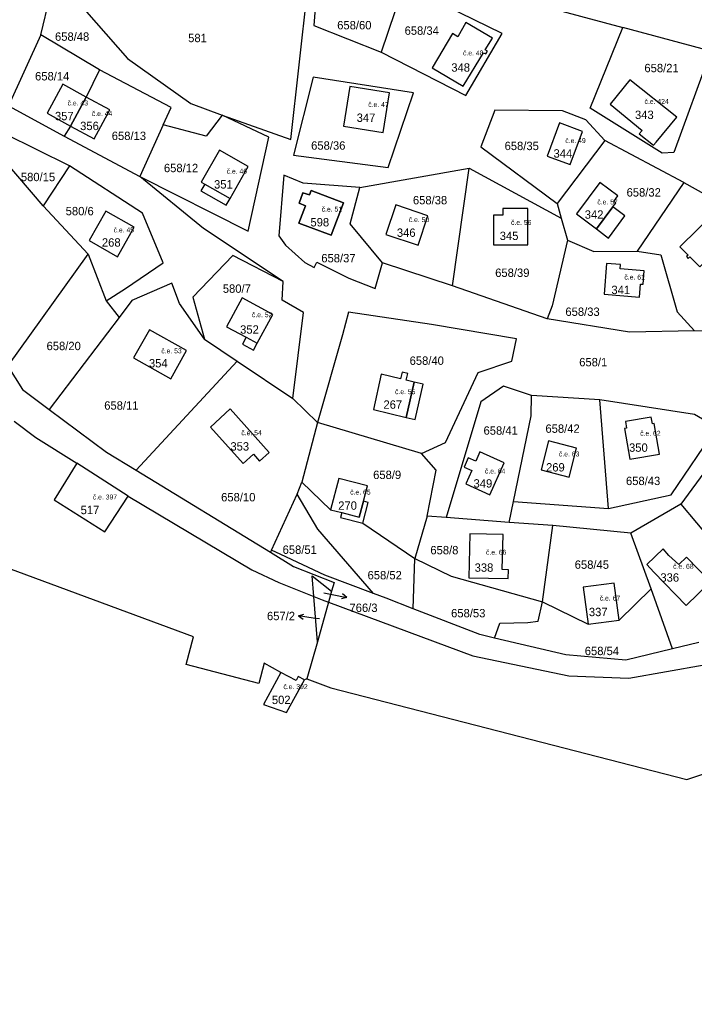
# Model space of a CAD drawing. Extents: x -887272 to -880188, y -1026687 to -1021896.
# Drawn here: x -883908.9 to -883771.9, y -1024223.4 to -1024025.9 of the extents above; entities that cross this region are included whole.
import ezdxf

# ---------------------------------------------------------------- set-up
doc = ezdxf.new("R2010")
doc.units = 0
for name, color, linetype in [('Definiční body', 7, 'Continuous'), ('Hranice parcel', 7, 'Continuous'), ('Parcelní čísla', 7, 'Continuous'), ('Polygon budovy', 7, 'Continuous'), ('Pop  PČ popisy', 7, 'Continuous'), ('Vnitřní kresba', 7, 'Continuous')]:
    doc.layers.add(name, color=color, linetype=linetype)

msp = doc.modelspace()

# ---------------------------------------------------------------- linework, layer by layer
at = {"layer": 'Hranice parcel'}
for p, q in [((-883904.58, -1024028.99), (-883901.68, -1024017.03)), ((-883832.76, -1024024.32), (-883835.54, -1024032.54)), ((-883904.58, -1024028.99), (-883911.13, -1024043.4)), ((-883892.65, -1024036.09), (-883904.58, -1024028.99)), ((-883768.62, -1024032.31), (-883786.49, -1024027.54)), ((-883892.65, -1024036.09), (-883895.35, -1024041.64)), ((-883895.35, -1024041.64), (-883898.54, -1024047.52)), ((-883911.13, -1024043.4), (-883899.81, -1024049.6)), ((-883898.54, -1024047.52), (-883899.81, -1024049.6)), ((-883879.74, -1024047.28), (-883884.47, -1024057.79)), ((-883898.73, -1024055.6), (-883911.85, -1024049.13)), ((-883899.81, -1024049.6), (-883884.47, -1024057.79)), ((-883790.11, -1024050.47), (-883799.82, -1024063.26)), ((-883774.14, -1024058.98), (-883790.11, -1024050.47)), ((-883815.27, -1024051.72), (-883799.82, -1024063.26)), ((-883904.07, -1024063.74), (-883912, -1024054.42)), ((-883898.73, -1024055.6), (-883904.07, -1024063.74)), ((-883839.82, -1024059.97), (-883817.65, -1024056.09)), ((-883821.04, -1024079.95), (-883817.65, -1024056.09)), ((-883817.65, -1024056.09), (-883798.98, -1024066.23)), ((-883774.14, -1024058.98), (-883783.59, -1024072.91)), ((-883904.07, -1024063.74), (-883895, -1024073.52)), ((-883799.82, -1024063.26), (-883798.98, -1024066.23)), ((-883798.98, -1024066.23), (-883797.72, -1024070.66)), ((-883797.72, -1024070.66), (-883800.86, -1024084)), ((-883911.25, -1024096.23), (-883895, -1024073.52)), ((-883895, -1024073.52), (-883891.31, -1024082.96)), ((-883821.04, -1024079.95), (-883835.23, -1024075.29)), ((-883801.81, -1024086.66), (-883821.04, -1024079.95)), ((-883891.31, -1024082.96), (-883888.71, -1024086.37)), ((-883886.12, -1024082.95), (-883888.71, -1024086.37)), ((-883800.86, -1024084), (-883801.81, -1024086.66)), ((-883888.71, -1024086.37), (-883902.86, -1024105.05)), ((-883785.14, -1024089.32), (-883801.81, -1024086.66)), ((-883771.96, -1024089.06), (-883785.14, -1024089.32)), ((-883871.37, -1024090.78), (-883864.73, -1024095.24)), ((-883864.73, -1024095.24), (-883885.25, -1024117.37)), ((-883864.73, -1024095.24), (-883853.46, -1024102.81)), ((-883791.15, -1024103.07), (-883805.04, -1024102.17)), ((-883848.46, -1024107.7), (-883853.46, -1024102.81)), ((-883789.37, -1024125.15), (-883791.15, -1024103.07)), ((-883848.46, -1024107.7), (-883851.6, -1024119.81)), ((-883827.31, -1024113.95), (-883848.46, -1024107.7)), ((-883886.86, -1024122.61), (-883897.3, -1024115.95)), ((-883885.25, -1024117.37), (-883857.97, -1024134.02)), ((-883852.59, -1024122.24), (-883851.6, -1024119.81)), ((-883851.6, -1024119.81), (-883845.79, -1024125.37)), ((-883857.76, -1024133.58), (-883852.59, -1024122.24)), ((-883809.55, -1024127.94), (-883808.64, -1024123.74)), ((-883808.64, -1024123.74), (-883789.37, -1024125.15)), ((-883774.69, -1024124.26), (-883784.9, -1024130.11)), ((-883826.22, -1024126.68), (-883828.69, -1024135.31)), ((-883822.34, -1024126.95), (-883826.22, -1024126.68)), ((-883809.55, -1024127.94), (-883822.34, -1024126.95)), ((-883800.69, -1024128.6), (-883809.55, -1024127.94)), ((-883839.24, -1024128.12), (-883828.69, -1024135.31)), ((-883802.78, -1024144.09), (-883800.69, -1024128.6)), ((-883784.9, -1024130.11), (-883800.69, -1024128.6)), ((-883780.77, -1024141.46), (-883784.9, -1024130.11)), ((-883857.76, -1024133.58), (-883857.97, -1024134.02)), ((-883829.01, -1024145.48), (-883828.69, -1024135.31)), ((-883845.58, -1024141.88), (-883846.21, -1024144.12)), ((-883794.52, -1024141.12), (-883793.52, -1024148.63)), ((-883787.26, -1024147.8), (-883780.77, -1024141.46)), ((-883776.38, -1024153.62), (-883780.77, -1024141.46)), ((-883848.47, -1024152.18), (-883849.17, -1024142.97)), ((-883846.21, -1024144.12), (-883848.47, -1024152.18)), ((-883802.78, -1024144.09), (-883793.52, -1024148.63)), ((-883793.52, -1024148.63), (-883787.26, -1024147.8)), ((-883848.47, -1024152.18), (-883850.59, -1024159.71)), ((-883771.09, -1024152.35), (-883776.38, -1024153.62)), ((-883850.59, -1024159.71), (-883851.11, -1024159.93))]:
    msp.add_line(p, q, dxfattribs=at)
for points in [[(-883899.62, -1024008.57), (-883860.9, -1024017.44), (-883848.52, -1024018.46), (-883830.95, -1024018.96), (-883822.3, -1024020.14), (-883798.84, -1024024.24), (-883786.49, -1024027.54)], [(-883867.76, -1024045.3), (-883853.82, -1024050.22), (-883850.5, -1024019.86), (-883889.5, -1024014.8), (-883900.86, -1024013.67)], [(-883901.68, -1024017.03), (-883886.96, -1024033.84), (-883874.14, -1024042.96), (-883867.76, -1024045.3)], [(-883835.54, -1024032.54), (-883818.36, -1024041.34), (-883811, -1024028.73), (-883830.95, -1024018.96), (-883832.76, -1024024.32)], [(-883832.76, -1024024.32), (-883848.72, -1024020.95), (-883849.18, -1024027.12), (-883835.54, -1024032.54)], [(-883814.31, -1024032.88), (-883813.98, -1024032.34), (-883814.4, -1024032.08), (-883812.92, -1024029.69), (-883818.33, -1024026.51), (-883820, -1024029.39), (-883821.08, -1024028.76), (-883825.2, -1024035.73), (-883818.87, -1024039.46), (-883814.73, -1024032.63), (-883814.31, -1024032.88)], [(-883768.62, -1024032.31), (-883776.16, -1024052.87), (-883778.5, -1024053.04), (-883793.12, -1024043.9), (-883786.49, -1024027.54)], [(-883879.74, -1024047.28), (-883878.15, -1024043.75), (-883892.65, -1024036.09)], [(-883895.35, -1024041.64), (-883900.14, -1024039.05), (-883903.32, -1024044.93), (-883898.54, -1024047.52)], [(-883853.32, -1024053.42), (-883834.12, -1024055.92), (-883828.96, -1024040.76), (-883849.32, -1024037.62), (-883853.32, -1024053.42)], [(-883785.08, -1024038.15), (-883789.08, -1024043.05), (-883782.58, -1024048.4), (-883783.15, -1024049.1), (-883780.27, -1024051.42), (-883779.72, -1024050.76), (-883775.54, -1024045.69), (-883785.08, -1024038.15)], [(-883843.14, -1024047.53), (-883835.09, -1024048.8), (-883833.83, -1024040.78), (-883841.88, -1024039.52), (-883843.14, -1024047.53)], [(-883898.54, -1024047.52), (-883893.75, -1024050.11), (-883890.57, -1024044.23), (-883895.35, -1024041.64)], [(-883790.11, -1024050.47), (-883793.99, -1024046.26), (-883798.72, -1024044.43), (-883812.43, -1024044.32), (-883815.27, -1024051.72)], [(-883884.47, -1024057.79), (-883862.5, -1024068.88), (-883858.34, -1024049.76), (-883867.76, -1024045.3)], [(-883867.76, -1024045.3), (-883871.06, -1024049.54), (-883879.74, -1024047.28)], [(-883794.66, -1024048.64), (-883799.35, -1024046.89), (-883801.84, -1024053.6), (-883797.16, -1024055.35), (-883794.66, -1024048.64)], [(-883866.19, -1024062.24), (-883862.5, -1024055.71), (-883868.29, -1024052.44), (-883872.04, -1024058.94), (-883871.33, -1024059.34), (-883872.1, -1024060.68), (-883866.95, -1024063.59), (-883866.19, -1024062.24)], [(-883891.31, -1024082.96), (-883887.41, -1024080.46), (-883879.76, -1024075.27), (-883883.92, -1024065.17), (-883898.73, -1024055.6)], [(-883855.39, -1024079.08), (-883871.6, -1024068.28), (-883884.47, -1024057.79)], [(-883839.82, -1024059.97), (-883851.38, -1024059.11), (-883855.27, -1024057.51), (-883856.27, -1024069.78), (-883854.92, -1024071.68), (-883851, -1024075.19)], [(-883788.54, -1024063.9), (-883787.94, -1024063.09), (-883788.29, -1024062.81), (-883787.49, -1024061.68), (-883791.17, -1024058.95), (-883795.9, -1024065.32), (-883791.86, -1024068.39), (-883789.42, -1024070.24), (-883786.08, -1024065.72), (-883788.54, -1024063.9)], [(-883851.41, -1024061.08), (-883850.08, -1024061.51), (-883849.74, -1024060.63), (-883843.18, -1024063.09), (-883845.65, -1024069.66), (-883852.21, -1024067.21), (-883850.9, -1024063.73), (-883852.14, -1024063.2), (-883851.41, -1024061.08)], [(-883846.21, -1024144.12), (-883816.92, -1024155.06), (-883797.46, -1024159.1), (-883785.24, -1024159.54), (-883770.02, -1024156.86), (-883754.54, -1024149.76), (-883741.82, -1024138.86), (-883718.28, -1024114.56), (-883704.22, -1024101.36), (-883679.66, -1024088.08), (-883640.76, -1024076.54), (-883629.62, -1024072.06), (-883617.24, -1024060.68)], [(-883835.23, -1024075.29), (-883841.84, -1024067.33), (-883839.82, -1024059.97)], [(-883774.14, -1024058.98), (-883765.97, -1024063.54), (-883750.88, -1024077.62), (-883742.25, -1024090.97), (-883754.31, -1024089.52), (-883771.96, -1024089.06)], [(-883889.05, -1024074.03), (-883885.63, -1024068.04), (-883891.36, -1024064.77), (-883894.78, -1024070.76), (-883889.05, -1024074.03)], [(-883832.57, -1024063.54), (-883834.56, -1024069.52), (-883828.01, -1024071.7), (-883826.02, -1024065.72), (-883832.57, -1024063.54)], [(-883805.74, -1024071.6), (-883805.76, -1024064.25), (-883810.86, -1024064.26), (-883810.86, -1024065.59), (-883812.76, -1024065.6), (-883812.74, -1024071.62), (-883805.74, -1024071.6)], [(-883773.25, -1024074.38), (-883772.9, -1024074.05), (-883770.89, -1024076.11), (-883769.13, -1024074.41), (-883766.95, -1024076.58), (-883761.97, -1024071.47), (-883765.87, -1024067.35), (-883765.62, -1024067.08), (-883767.68, -1024064.92), (-883774.9, -1024072), (-883773.24, -1024073.7), (-883773.59, -1024074.02), (-883773.25, -1024074.38)], [(-883797.72, -1024070.66), (-883792.36, -1024072.96), (-883783.59, -1024072.91)], [(-883855.39, -1024079.08), (-883865.64, -1024073.78), (-883873.75, -1024082.22), (-883871.37, -1024090.78)], [(-883783.59, -1024072.91), (-883778.79, -1024073.63), (-883775.45, -1024085.25), (-883771.96, -1024089.06)], [(-883851, -1024075.19), (-883849.14, -1024076.21), (-883848.6, -1024075.14), (-883842.11, -1024078.39)], [(-883842.11, -1024078.39), (-883836.75, -1024080.5), (-883835.23, -1024075.29)], [(-883787.01, -1024076.49), (-883786.94, -1024075.65), (-883789.78, -1024075.42), (-883790.28, -1024081.65), (-883783.12, -1024082.22), (-883782.9, -1024079.58), (-883782.39, -1024079.62), (-883782.18, -1024076.88), (-883787.01, -1024076.49)], [(-883871.37, -1024090.78), (-883876.44, -1024083.54), (-883877.98, -1024079.41), (-883886.12, -1024082.95)], [(-883853.46, -1024102.81), (-883851.26, -1024085.39), (-883855.59, -1024082.86), (-883855.39, -1024079.08)], [(-883863.67, -1024091.75), (-883861.44, -1024092.99), (-883860.69, -1024091.61), (-883857.51, -1024085.77), (-883863.7, -1024082.4), (-883866.88, -1024088.24), (-883862.93, -1024090.39), (-883863.67, -1024091.75)], [(-883827.31, -1024113.95), (-883822.48, -1024111.73), (-883815.82, -1024097.56), (-883809.04, -1024095.22), (-883808.05, -1024090.68), (-883825.31, -1024087.78), (-883842.14, -1024085.28), (-883843.37, -1024089.91), (-883848.46, -1024107.7)], [(-883878.22, -1024098.8), (-883875.02, -1024093.1), (-883882.54, -1024088.88), (-883885.74, -1024094.58), (-883878.22, -1024098.8)], [(-883911.25, -1024096.23), (-883908.31, -1024100.98), (-883902.86, -1024105.05)], [(-883835.5, -1024097.87), (-883837.09, -1024105.03), (-883830.43, -1024106.65), (-883828.63, -1024107.09), (-883827.02, -1024099.91), (-883828.8, -1024099.48), (-883830.44, -1024099.09), (-883830.12, -1024097.75), (-883831.29, -1024097.47), (-883831.61, -1024098.8), (-883835.5, -1024097.87)], [(-883805.04, -1024102.17), (-883810.73, -1024100.34), (-883815.28, -1024103.49), (-883822.34, -1024126.95)], [(-883808.64, -1024123.74), (-883805.07, -1024106.32), (-883805.04, -1024102.17)], [(-883789.37, -1024125.15), (-883776.68, -1024122.39), (-883767.41, -1024108.72), (-883771.96, -1024106.03), (-883791.15, -1024103.07)], [(-883902.86, -1024105.05), (-883891.27, -1024113.69), (-883885.25, -1024117.37)], [(-883870.17, -1024108.63), (-883863.54, -1024116.02), (-883861.44, -1024114.13), (-883860.21, -1024115.5), (-883858.25, -1024113.75), (-883866.19, -1024104.9), (-883870.17, -1024108.63)], [(-883909.98, -1024107.42), (-883905.62, -1024110.7), (-883897.3, -1024115.95)], [(-883780.72, -1024106.61), (-883785.96, -1024107.49), (-883785.74, -1024108.83), (-883786.17, -1024108.9), (-883785.05, -1024115.09), (-883779.07, -1024114.08), (-883780.12, -1024107.89), (-883780.5, -1024107.95), (-883780.72, -1024106.61)], [(-883755.65, -1024112.37), (-883763.88, -1024109.51), (-883774.69, -1024124.26)], [(-883803.06, -1024117.29), (-883797.35, -1024118.75), (-883795.86, -1024112.89), (-883801.57, -1024111.43), (-883803.06, -1024117.29)], [(-883826.22, -1024126.68), (-883824.36, -1024117.36), (-883827.31, -1024113.95)], [(-883816.31, -1024115.53), (-883817.88, -1024114.84), (-883818.71, -1024116.74), (-883817.14, -1024117.43), (-883818.33, -1024120.16), (-883813.45, -1024122.35), (-883810.54, -1024115.86), (-883815.48, -1024113.64), (-883816.31, -1024115.53)], [(-883897.3, -1024115.95), (-883901.84, -1024123.36), (-883891.56, -1024129.87), (-883886.86, -1024122.61)], [(-883839.24, -1024128.12), (-883838.14, -1024123.89), (-883839.11, -1024123.64), (-883838.31, -1024120.56), (-883844.14, -1024119.04), (-883845.79, -1024125.37)], [(-883886.86, -1024122.61), (-883861.76, -1024137.6), (-883856.28, -1024140.14), (-883849.17, -1024142.97)], [(-883837.08, -1024142.37), (-883848.38, -1024129.33), (-883852.59, -1024122.24)], [(-883845.79, -1024125.37), (-883843.51, -1024125.96), (-883843.76, -1024126.94), (-883839.24, -1024128.12)], [(-883774.69, -1024124.26), (-883768.39, -1024131.8), (-883765.84, -1024134.88)], [(-883810.78, -1024130.4), (-883817.56, -1024130.29), (-883817.73, -1024139.21), (-883809.73, -1024139.36), (-883809.66, -1024137.55), (-883810.95, -1024137.52), (-883810.78, -1024130.4)], [(-883855.91, -1024158.43), (-883859.24, -1024156.52), (-883860.34, -1024160.64), (-883875.1, -1024156.8), (-883873.62, -1024151.2), (-883922.82, -1024133), (-883946.68, -1024157.76), (-883998.42, -1024167.88), (-884017.26, -1024191.06), (-884045.27, -1024222.29), (-884069.78, -1024223.36)], [(-883837.08, -1024142.37), (-883846.93, -1024138.63), (-883855.9, -1024134.45), (-883857.76, -1024133.58)], [(-883777.14, -1024134.64), (-883778.34, -1024133.34), (-883781.61, -1024136.5)], [(-883857.97, -1024134.02), (-883853.29, -1024136.88), (-883845.09, -1024140.15), (-883845.58, -1024141.88)], [(-883828.69, -1024135.31), (-883821.35, -1024138.89), (-883802.78, -1024144.09)], [(-883773.56, -1024134.99), (-883775.1, -1024136.47), (-883777.14, -1024134.64)], [(-883773.62, -1024144.81), (-883768.71, -1024140), (-883773.56, -1024134.99)], [(-883781.61, -1024136.5), (-883780.21, -1024138.05), (-883773.62, -1024144.81)], [(-883849.17, -1024142.97), (-883849.49, -1024138.77), (-883845.58, -1024141.88)], [(-883787.26, -1024147.8), (-883788.26, -1024140.29), (-883794.52, -1024141.12)], [(-883849.17, -1024142.97), (-883847.5, -1024143.64), (-883846.21, -1024144.12)], [(-883829.01, -1024145.48), (-883834.53, -1024143.33), (-883837.08, -1024142.37)], [(-883812.51, -1024151.44), (-883815.49, -1024150.73), (-883829.01, -1024145.48)], [(-883812.51, -1024151.44), (-883811.42, -1024148.42), (-883805.74, -1024148.27), (-883803.69, -1024147.97), (-883802.78, -1024144.09)], [(-883776.38, -1024153.62), (-883785.87, -1024155.89), (-883798.06, -1024154.86), (-883812.51, -1024151.44)], [(-883855.91, -1024158.43), (-883859.37, -1024164.93), (-883854.7, -1024166.54), (-883851.11, -1024159.93)], [(-883851.11, -1024159.93), (-883852.36, -1024159.25), (-883852.76, -1024160.05), (-883855.91, -1024158.43)], [(-883850.59, -1024159.71), (-883845.76, -1024161.5), (-883773.48, -1024180.1), (-883759.24, -1024175.32)]]:
    msp.add_lwpolyline(points, dxfattribs=at)
at = {"layer": 'Polygon budovy'}
for points in [[(-883818.87, -1024039.46), (-883814.73, -1024032.63), (-883814.31, -1024032.88), (-883813.98, -1024032.34), (-883814.4, -1024032.08), (-883812.92, -1024029.69), (-883818.33, -1024026.51), (-883820, -1024029.39), (-883821.08, -1024028.76), (-883825.2, -1024035.73)], [(-883903.32, -1024044.93), (-883898.54, -1024047.52), (-883895.35, -1024041.64), (-883900.14, -1024039.05)], [(-883775.54, -1024045.69), (-883785.08, -1024038.15), (-883789.08, -1024043.05), (-883782.58, -1024048.4), (-883783.15, -1024049.1), (-883780.27, -1024051.42), (-883779.72, -1024050.76)], [(-883841.88, -1024039.52), (-883843.14, -1024047.53), (-883835.09, -1024048.8), (-883833.83, -1024040.78)], [(-883895.35, -1024041.64), (-883898.54, -1024047.52), (-883893.75, -1024050.11), (-883890.57, -1024044.23)], [(-883801.84, -1024053.6), (-883797.16, -1024055.35), (-883794.66, -1024048.64), (-883799.35, -1024046.89)], [(-883862.5, -1024055.71), (-883868.29, -1024052.44), (-883872.04, -1024058.94), (-883871.33, -1024059.34), (-883866.19, -1024062.24)], [(-883788.54, -1024063.9), (-883787.94, -1024063.09), (-883788.29, -1024062.81), (-883787.49, -1024061.68), (-883791.17, -1024058.95), (-883795.9, -1024065.32), (-883791.86, -1024068.39)], [(-883849.74, -1024060.63), (-883850.08, -1024061.51), (-883851.41, -1024061.08), (-883852.14, -1024063.2), (-883850.9, -1024063.73), (-883852.21, -1024067.21), (-883845.65, -1024069.66), (-883843.18, -1024063.09)], [(-883891.36, -1024064.77), (-883894.78, -1024070.76), (-883889.05, -1024074.03), (-883885.63, -1024068.04)], [(-883834.56, -1024069.52), (-883828.01, -1024071.7), (-883826.02, -1024065.72), (-883832.57, -1024063.54)], [(-883805.76, -1024064.25), (-883810.86, -1024064.26), (-883810.86, -1024065.59), (-883812.76, -1024065.6), (-883812.74, -1024071.62), (-883805.74, -1024071.6)], [(-883773.59, -1024074.02), (-883773.25, -1024074.38), (-883772.9, -1024074.05), (-883770.89, -1024076.11), (-883769.13, -1024074.41), (-883765.16, -1024070.5), (-883767.03, -1024068.53), (-883765.87, -1024067.35), (-883765.62, -1024067.08), (-883767.68, -1024064.92), (-883774.9, -1024072), (-883773.24, -1024073.7)], [(-883789.78, -1024075.42), (-883790.28, -1024081.65), (-883783.12, -1024082.22), (-883782.9, -1024079.58), (-883782.39, -1024079.62), (-883782.18, -1024076.88), (-883787.01, -1024076.49), (-883786.94, -1024075.65)], [(-883863.7, -1024082.4), (-883866.88, -1024088.24), (-883862.93, -1024090.39), (-883860.69, -1024091.61), (-883857.51, -1024085.77)], [(-883882.54, -1024088.88), (-883885.74, -1024094.58), (-883878.22, -1024098.8), (-883875.02, -1024093.1)], [(-883837.09, -1024105.03), (-883830.43, -1024106.65), (-883828.8, -1024099.48), (-883830.44, -1024099.09), (-883830.12, -1024097.75), (-883831.29, -1024097.47), (-883831.61, -1024098.8), (-883835.5, -1024097.87)], [(-883866.19, -1024104.9), (-883870.17, -1024108.63), (-883863.54, -1024116.02), (-883861.44, -1024114.13), (-883860.21, -1024115.5), (-883858.25, -1024113.75)], [(-883785.96, -1024107.49), (-883785.74, -1024108.83), (-883786.17, -1024108.9), (-883785.05, -1024115.09), (-883779.07, -1024114.08), (-883780.12, -1024107.89), (-883780.5, -1024107.95), (-883780.72, -1024106.61)], [(-883801.57, -1024111.43), (-883803.06, -1024117.29), (-883797.35, -1024118.75), (-883795.86, -1024112.89)], [(-883815.48, -1024113.64), (-883816.31, -1024115.53), (-883817.88, -1024114.84), (-883818.71, -1024116.74), (-883817.14, -1024117.43), (-883818.33, -1024120.16), (-883813.45, -1024122.35), (-883810.54, -1024115.86)], [(-883897.3, -1024115.95), (-883901.84, -1024123.36), (-883891.56, -1024129.87), (-883886.86, -1024122.61)], [(-883845.79, -1024125.37), (-883843.51, -1024125.96), (-883839.96, -1024126.89), (-883839.11, -1024123.64), (-883838.31, -1024120.56), (-883844.14, -1024119.04)], [(-883817.73, -1024139.21), (-883809.73, -1024139.36), (-883809.66, -1024137.55), (-883810.95, -1024137.52), (-883810.78, -1024130.4), (-883817.56, -1024130.29)], [(-883780.21, -1024138.05), (-883773.62, -1024144.81), (-883768.71, -1024140), (-883773.56, -1024134.99), (-883775.1, -1024136.47), (-883777.14, -1024134.64), (-883778.34, -1024133.34), (-883781.61, -1024136.5)], [(-883794.52, -1024141.12), (-883793.52, -1024148.63), (-883787.26, -1024147.8), (-883788.26, -1024140.29)], [(-883855.91, -1024158.43), (-883859.37, -1024164.93), (-883854.7, -1024166.54), (-883851.11, -1024159.93), (-883852.36, -1024159.25), (-883852.76, -1024160.05)]]:
    msp.add_lwpolyline(points, close=True, dxfattribs=at)
at = {"layer": 'Pop  PČ popisy'}
for p, q in [((-883847.14, -1024142.27), (-883845.44, -1024142.59)), ((-883845.44, -1024142.59), (-883842.49, -1024143.16)), ((-883842.49, -1024143.16), (-883843.57, -1024143.46)), ((-883842.49, -1024143.16), (-883843.38, -1024142.48)), ((-883852.3, -1024146.94), (-883851.24, -1024146.59)), ((-883849.33, -1024147.36), (-883852.3, -1024146.94)), ((-883852.3, -1024146.94), (-883851.38, -1024147.58)), ((-883848.01, -1024147.54), (-883849.33, -1024147.36))]:
    msp.add_line(p, q, dxfattribs=at)
at = {"layer": 'Vnitřní kresba'}
for p, q in [((-883871.33, -1024059.34), (-883866.19, -1024062.24)), ((-883788.54, -1024063.9), (-883791.86, -1024068.39)), ((-883862.93, -1024090.39), (-883860.69, -1024091.61)), ((-883828.8, -1024099.48), (-883830.43, -1024106.65)), ((-883839.11, -1024123.64), (-883839.96, -1024126.89)), ((-883843.51, -1024125.96), (-883839.96, -1024126.89))]:
    msp.add_line(p, q, dxfattribs=at)

# ---------------------------------------------------------------- texts
at = {"layer": 'Definiční body'}
for s, p in [('č.e. 48', (-883818.91, -1024033.19)), ('č.e. 43', (-883899.15, -1024043.34)), ('č.e. 47', (-883838.15, -1024043.66)), ('č.e. 424', (-883782.09, -1024043.02)), ('č.e. 44', (-883894.22, -1024045.49)), ('č.e. 49', (-883798.16, -1024050.97)), ('č.e. 46', (-883866.87, -1024057.18)), ('č.e. 57', (-883791.66, -1024063.43)), ('č.e. 51', (-883847.59, -1024064.88)), ('č.e. 50', (-883829.92, -1024067.01)), ('č.e. 56', (-883809.17, -1024067.58)), ('č.e. 45', (-883889.8, -1024069.1)), ('č.e. 61', (-883786.17, -1024078.68)), ('č.e. 52', (-883861.75, -1024086.31)), ('č.e. 53', (-883880.14, -1024093.64)), ('č.e. 55', (-883832.71, -1024101.93)), ('č.e. 54', (-883863.9, -1024110.27)), ('č.e. 62', (-883782.97, -1024110.36)), ('č.e. 63', (-883799.46, -1024114.57)), ('č.e. 64', (-883814.47, -1024118.03)), ('č.e. 65', (-883841.81, -1024122.31)), ('č.e. 397', (-883894.02, -1024123.3)), ('č.e. 66', (-883814.25, -1024134.51)), ('č.e. 68', (-883776.28, -1024137.36)), ('č.e. 67', (-883791.17, -1024143.82)), ('č.e. 392', (-883855.35, -1024161.79))]:
    msp.add_text(s, height=1, dxfattribs=at).set_placement(p)
at = {"layer": 'Parcelní čísla'}
for s, p in [('658/60', (-883844.44, -1024027.9)), ('658/34', (-883830.77, -1024029)), ('658/48', (-883901.7, -1024030.22)), ('581', (-883874.68, -1024030.5)), ('348', (-883821.29, -1024036.49)), ('658/21', (-883782.11, -1024036.6)), ('658/14', (-883905.74, -1024038.26)), ('357', (-883901.71, -1024046.34)), ('347', (-883840.49, -1024046.68)), ('343', (-883784.02, -1024046.09)), ('356', (-883896.6, -1024048.34)), ('658/13', (-883890.18, -1024050.36)), ('658/36', (-883849.73, -1024052.32)), ('658/35', (-883810.48, -1024052.4)), ('344', (-883800.55, -1024053.93)), ('580/15', (-883908.62, -1024058.71)), ('658/12', (-883879.6, -1024056.88)), ('351', (-883869.43, -1024060.2)), ('658/32', (-883785.73, -1024061.83)), ('658/38', (-883829.08, -1024063.41)), ('580/6', (-883899.53, -1024065.63)), ('342', (-883794.22, -1024066.33)), ('598', (-883849.87, -1024067.89)), ('346', (-883832.33, -1024070.01)), ('268', (-883892.18, -1024071.99)), ('345', (-883811.47, -1024070.65)), ('658/37', (-883847.67, -1024075.18)), ('658/39', (-883812.39, -1024078.14)), ('580/7', (-883867.65, -1024081.36)), ('341', (-883788.81, -1024081.62)), ('658/33', (-883798.14, -1024086.05)), ('352', (-883864.14, -1024089.66)), ('658/20', (-883903.41, -1024093)), ('658/40', (-883829.75, -1024095.98)), ('658/1', (-883795.34, -1024096.28)), ('354', (-883882.64, -1024096.5)), ('658/11', (-883891.71, -1024105.08)), ('267', (-883835.06, -1024104.89)), ('658/42', (-883802.19, -1024109.77)), ('658/41', (-883814.75, -1024110.16)), ('353', (-883866.11, -1024113.38)), ('350', (-883785.23, -1024113.62)), ('269', (-883802.07, -1024117.62)), ('658/9', (-883837.15, -1024119.15)), ('349', (-883816.78, -1024120.89)), ('658/43', (-883785.85, -1024120.38)), ('658/10', (-883867.99, -1024123.69)), ('270', (-883844.23, -1024125.39)), ('517', (-883896.5, -1024126.28)), ('658/51', (-883855.52, -1024134.34)), ('658/8', (-883825.54, -1024134.43)), ('658/45', (-883796.25, -1024137.37)), ('658/52', (-883838.28, -1024139.51)), ('338', (-883816.56, -1024137.97)), ('336', (-883778.87, -1024139.98)), ('766/3', (-883841.95, -1024146.13)), ('658/53', (-883821.33, -1024147.22)), ('337', (-883793.38, -1024146.98)), ('657/2', (-883858.69, -1024147.8)), ('658/54', (-883794.21, -1024154.89)), ('502', (-883857.7, -1024164.82))]:
    msp.add_text(s, height=1.7, dxfattribs=at).set_placement(p)

doc.saveas('drawing.dxf')
